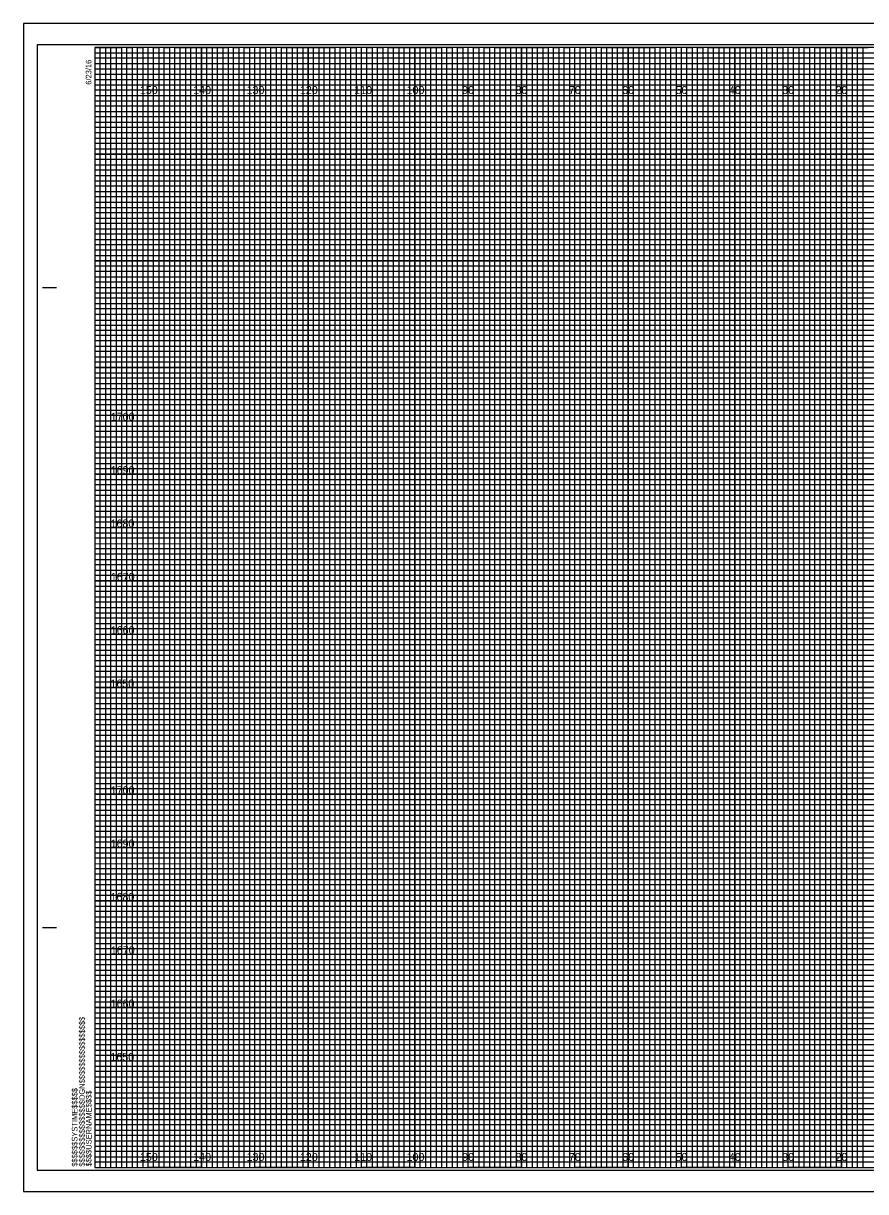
# Model space of a CAD drawing. Extents: x 656 to 993, y -2 to 2857.
# Drawn here: x 656.3 to 814.2, y 878.3 to 1097.3 of the extents above; entities that cross this region are included whole.
import ezdxf

# ---------------------------------------------------------------- set-up
doc = ezdxf.new("R2010")
doc.units = 0
for name, color, linetype in [('Prop RDY Alternate Text Blue', 7, 'Continuous'), ('Prop Retaining Wall', 7, 'Continuous'), ('Prop SS Cut Line', 7, 'Continuous'), ('Prop SS Fill Line', 7, 'Continuous'), ('Prop SS Transition Line', 7, 'Continuous'), ('Raster_Level_0', 7, 'Continuous'), ('Raster_Level_3', 7, 'Continuous'), ('Scratch_Level_3', 7, 'Continuous'), ('Scratch_Level_7', 7, 'Continuous'), ('Typical Guardrail CELL', 7, 'Continuous'), ('Typical Text Asphalt at Bridge Approach CELL', 7, 'Continuous')]:
    doc.layers.add(name, color=color, linetype=linetype)

msp = doc.modelspace()

# ---------------------------------------------------------------- linework, layer by layer
at = {"layer": 'Prop RDY Alternate Text Blue'}
for p, q in [((679.74, 882.8), (679.74, 1092.8)), ((689.74, 882.8), (689.74, 1092.8)), ((699.74, 882.8), (699.74, 1092.8)), ((709.74, 882.8), (709.74, 1092.8)), ((719.74, 882.8), (719.74, 1092.8)), ((729.74, 882.8), (729.74, 1092.8)), ((739.74, 882.8), (739.74, 1092.8)), ((749.74, 882.8), (749.74, 1092.8)), ((759.74, 882.8), (759.74, 1092.8)), ((769.74, 882.8), (769.74, 1092.8)), ((779.74, 882.8), (779.74, 1092.8)), ((789.74, 882.8), (789.74, 1092.8)), ((799.74, 882.8), (799.74, 1092.8)), ((809.74, 882.8), (809.74, 1092.8)), ((669.74, 1082.8), (989.74, 1082.8)), ((669.74, 1072.8), (989.74, 1072.8)), ((669.74, 1062.8), (989.74, 1062.8)), ((669.74, 1052.8), (989.74, 1052.8)), ((669.74, 1042.8), (989.74, 1042.8)), ((669.74, 1032.8), (989.74, 1032.8)), ((669.74, 1022.8), (989.74, 1022.8)), ((669.74, 1012.8), (989.74, 1012.8)), ((669.74, 1002.8), (989.74, 1002.8)), ((669.74, 992.8), (989.74, 992.8)), ((669.74, 982.8), (989.74, 982.8)), ((669.74, 972.8), (989.74, 972.8)), ((669.74, 962.8), (989.74, 962.8)), ((669.74, 952.8), (989.74, 952.8)), ((669.74, 942.8), (989.74, 942.8)), ((669.74, 932.8), (989.74, 932.8)), ((669.74, 922.8), (989.74, 922.8)), ((669.74, 912.8), (989.74, 912.8)), ((669.74, 902.8), (989.74, 902.8)), ((669.74, 892.8), (989.74, 892.8))]:
    msp.add_line(p, q, dxfattribs=at)
at = {"layer": 'Prop Retaining Wall'}
for p, q in [((659.94, 1047.8), (662.44, 1047.8)), ((660.04, 1047.8), (662.54, 1047.8)), ((659.94, 927.8), (662.44, 927.8)), ((660.04, 927.8), (662.54, 927.8)), ((669.74, 882.8), (669.74, 882.8)), ((669.74, 882.8), (669.74, 882.8)), ((669.74, 882.8), (669.74, 882.8)), ((669.74, 882.8), (669.74, 882.8)), ((669.74, 882.8), (669.74, 882.8)), ((669.74, 882.8), (669.74, 882.8)), ((669.74, 882.8), (669.74, 882.8))]:
    msp.add_line(p, q, dxfattribs=at)
msp.add_lwpolyline([(989.74, 1092.8), (669.74, 1092.8), (669.74, 882.8), (989.74, 882.8)], close=True, dxfattribs=at)
at = {"layer": 'Prop SS Cut Line'}
for points in [[(669.74, 1092.8), (674.74, 1092.8), (674.74, 882.8), (684.74, 882.8), (684.74, 1092.8), (694.74, 1092.8), (694.74, 882.8), (704.74, 882.8), (704.74, 1092.8), (714.74, 1092.8), (714.74, 882.8), (724.74, 882.8), (724.74, 1092.8), (734.74, 1092.8), (734.74, 882.8), (744.74, 882.8), (744.74, 1092.8), (754.74, 1092.8), (754.74, 882.8), (764.74, 882.8), (764.74, 1092.8), (774.74, 1092.8), (774.74, 882.8), (784.74, 882.8), (784.74, 1092.8), (794.74, 1092.8), (794.74, 882.8), (804.74, 882.8), (804.74, 1092.8), (814.74, 1092.8)], [(669.74, 1087.8), (944.74, 1087.8)], [(669.74, 1067.8), (989.74, 1067.8), (989.74, 1077.8), (669.74, 1077.8)], [(669.74, 1047.8), (989.74, 1047.8), (989.74, 1057.8), (669.74, 1057.8)], [(669.74, 1027.8), (989.74, 1027.8), (989.74, 1037.8), (669.74, 1037.8)], [(669.74, 1007.8), (989.74, 1007.8), (989.74, 1017.8), (669.74, 1017.8)], [(669.74, 987.8), (989.74, 987.8), (989.74, 997.8), (669.74, 997.8)], [(669.74, 967.8), (989.74, 967.8), (989.74, 977.8), (669.74, 977.8)], [(669.74, 947.8), (989.74, 947.8), (989.74, 957.8), (669.74, 957.8)], [(669.74, 927.8), (989.74, 927.8), (989.74, 937.8), (669.74, 937.8)], [(669.74, 907.8), (989.74, 907.8), (989.74, 917.8), (669.74, 917.8)], [(669.74, 887.8), (989.74, 887.8), (989.74, 897.8), (669.74, 897.8)]]:
    msp.add_lwpolyline(points, dxfattribs=at)
at = {"layer": 'Prop SS Fill Line'}
for p, q in [((679.74, 1092.8), (669.74, 1092.8)), ((679.74, 882.8), (679.74, 1092.8)), ((699.74, 1092.8), (689.74, 1092.8)), ((689.74, 1092.8), (689.74, 882.8)), ((699.74, 882.8), (699.74, 1092.8)), ((719.74, 1092.8), (709.74, 1092.8)), ((709.74, 1092.8), (709.74, 882.8)), ((719.74, 882.8), (719.74, 1092.8)), ((739.74, 1092.8), (729.74, 1092.8)), ((729.74, 1092.8), (729.74, 882.8)), ((739.74, 882.8), (739.74, 1092.8)), ((759.74, 1092.8), (749.74, 1092.8)), ((749.74, 1092.8), (749.74, 882.8)), ((759.74, 882.8), (759.74, 1092.8)), ((779.74, 1092.8), (769.74, 1092.8)), ((769.74, 1092.8), (769.74, 882.8)), ((779.74, 882.8), (779.74, 1092.8)), ((799.74, 1092.8), (789.74, 1092.8)), ((789.74, 1092.8), (789.74, 882.8)), ((799.74, 882.8), (799.74, 1092.8)), ((819.74, 1092.8), (809.74, 1092.8)), ((809.74, 1092.8), (809.74, 882.8)), ((689.74, 882.8), (679.74, 882.8)), ((709.74, 882.8), (699.74, 882.8)), ((729.74, 882.8), (719.74, 882.8)), ((749.74, 882.8), (739.74, 882.8)), ((769.74, 882.8), (759.74, 882.8)), ((789.74, 882.8), (779.74, 882.8)), ((809.74, 882.8), (799.74, 882.8))]:
    msp.add_line(p, q, dxfattribs=at)
for points in [[(669.74, 1082.8), (989.74, 1082.8), (989.74, 1072.8), (669.74, 1072.8)], [(669.74, 1062.8), (989.74, 1062.8), (989.74, 1052.8), (669.74, 1052.8)], [(669.74, 1042.8), (989.74, 1042.8), (989.74, 1032.8), (669.74, 1032.8)], [(669.74, 1022.8), (989.74, 1022.8), (989.74, 1012.8), (669.74, 1012.8)], [(669.74, 1002.8), (989.74, 1002.8), (989.74, 992.8), (669.74, 992.8)], [(669.74, 982.8), (989.74, 982.8), (989.74, 972.8), (669.74, 972.8)], [(669.74, 962.8), (989.74, 962.8), (989.74, 952.8), (669.74, 952.8)], [(669.74, 942.8), (989.74, 942.8), (989.74, 932.8), (669.74, 932.8)], [(669.74, 922.8), (989.74, 922.8), (989.74, 912.8), (669.74, 912.8)], [(669.74, 902.8), (989.74, 902.8), (989.74, 892.8), (669.74, 892.8)]]:
    msp.add_lwpolyline(points, dxfattribs=at)
at = {"layer": 'Prop SS Transition Line'}
for p, q in [((669.74, 1091.8), (929.74, 1091.8)), ((929.74, 1090.78), (669.74, 1090.78)), ((669.74, 1090.78), (669.74, 1089.8)), ((669.74, 1089.8), (929.74, 1089.8)), ((929.74, 1088.69), (669.74, 1088.69)), ((669.74, 1088.69), (669.74, 1086.8)), ((669.74, 1086.8), (989.74, 1086.8))]:
    msp.add_line(p, q, dxfattribs=at)
for points in [[(669.74, 1085.8), (939.74, 1085.8), (989.74, 1085.8), (989.74, 1084.8), (669.74, 1084.8)], [(669.74, 1083.8), (989.74, 1083.8), (989.74, 1081.8), (669.74, 1081.8)], [(669.74, 1080.8), (989.74, 1080.8), (989.74, 1079.8), (669.74, 1079.78)], [(669.74, 1078.8), (989.74, 1078.8), (989.74, 1076.8), (669.74, 1076.8)], [(669.74, 1075.8), (989.74, 1075.8), (989.74, 1074.8), (669.74, 1074.8)], [(669.74, 1073.8), (989.74, 1073.8), (989.74, 1071.8), (669.74, 1071.8)], [(669.74, 1070.8), (989.74, 1070.8), (989.74, 1069.8), (669.74, 1069.8)], [(669.74, 1068.8), (989.74, 1068.8), (989.74, 1066.8), (669.74, 1066.8)], [(669.74, 1065.8), (989.74, 1065.8), (989.74, 1064.8), (669.74, 1064.8)], [(669.74, 1063.8), (989.74, 1063.8), (989.74, 1061.8), (669.74, 1061.8)], [(669.74, 1060.8), (989.74, 1060.8), (989.74, 1059.8), (669.74, 1059.8)], [(669.74, 1058.8), (989.74, 1058.8), (989.74, 1056.75), (989.74, 1055.8), (989.74, 1054.8), (669.74, 1054.8)], [(669.74, 1056.8), (989.74, 1056.8), (989.74, 1055.8), (669.74, 1055.8)], [(669.74, 1053.8), (989.74, 1053.8), (989.74, 1051.8), (669.74, 1051.83)], [(669.74, 1051.83), (989.74, 1051.8), (989.74, 1050.8), (669.74, 1050.8)], [(669.74, 1049.8), (989.74, 1049.8), (989.74, 1048.8), (669.74, 1048.8)], [(669.74, 1046.8), (989.74, 1046.8), (989.74, 1045.8), (669.74, 1045.8)], [(669.74, 1044.8), (989.74, 1044.8), (989.74, 1043.8), (669.74, 1043.8)], [(669.67, 1041.69), (989.74, 1041.69), (989.74, 1040.68), (669.67, 1040.68)], [(669.74, 1039.8), (989.74, 1039.8), (989.74, 1038.8), (669.74, 1038.8)], [(669.74, 1036.8), (989.74, 1036.8), (989.74, 1035.8), (669.74, 1035.8)], [(669.74, 1034.8), (989.74, 1034.8), (989.74, 1033.8), (669.74, 1033.8)], [(669.74, 1031.8), (989.74, 1031.8), (989.74, 1030.8), (669.74, 1030.8)], [(669.74, 1029.8), (989.74, 1029.8), (989.74, 1028.8), (669.74, 1028.8)], [(669.74, 1026.8), (989.74, 1026.8), (989.74, 1025.8), (669.74, 1025.8)], [(669.74, 1024.8), (989.74, 1024.8), (989.74, 1023.8), (669.74, 1023.8)], [(669.74, 1021.8), (989.74, 1021.8), (989.73, 1020.78), (669.74, 1020.8)], [(669.74, 1019.8), (989.74, 1019.8), (989.74, 1018.8), (669.74, 1018.8)], [(669.74, 1016.8), (989.74, 1016.8), (989.74, 1015.8), (669.74, 1015.8)], [(669.74, 1014.8), (989.74, 1014.8), (989.74, 1013.8), (669.74, 1013.8)], [(669.74, 1011.8), (989.74, 1011.8), (989.74, 1010.8), (669.74, 1010.8)], [(669.74, 1009.8), (989.74, 1009.8), (989.74, 1008.8), (669.74, 1008.8)], [(669.74, 1006.8), (989.74, 1006.8), (989.74, 1005.8), (669.74, 1005.8)], [(669.74, 1004.8), (989.74, 1004.8), (989.74, 1003.8), (669.74, 1003.8)], [(669.74, 1001.8), (989.74, 1001.8), (989.74, 1000.8), (669.74, 1000.8)], [(669.74, 999.79), (989.81, 999.71), (989.74, 998.8), (669.74, 998.8)], [(669.74, 996.8), (989.74, 996.8), (989.74, 995.8), (669.74, 995.8)], [(669.74, 994.8), (989.74, 994.8), (989.74, 993.8), (669.74, 993.8)], [(669.74, 991.8), (989.74, 991.8), (989.74, 990.8), (669.74, 990.8)], [(669.74, 989.8), (989.74, 989.8), (989.74, 988.8), (669.74, 988.8)], [(669.74, 986.8), (989.74, 986.8), (989.74, 985.8), (669.74, 985.8)], [(669.74, 984.8), (989.74, 984.8), (989.74, 983.8), (669.74, 983.8)], [(669.74, 981.8), (989.74, 981.8), (989.74, 980.8), (669.74, 980.8)], [(669.74, 979.8), (989.74, 979.8), (989.74, 978.8), (669.74, 978.8)], [(669.74, 976.8), (989.74, 976.8), (989.74, 975.8), (669.74, 975.8)], [(669.74, 974.8), (989.74, 974.8), (989.74, 973.8), (669.74, 973.8)], [(669.74, 971.8), (989.74, 971.8), (989.74, 970.8), (669.74, 970.8)], [(669.74, 969.8), (989.74, 969.8), (989.74, 968.8), (669.74, 968.8)], [(669.74, 966.8), (989.74, 966.8), (989.74, 965.8), (669.74, 965.8)], [(669.74, 964.8), (989.74, 964.8), (989.74, 963.8), (669.74, 963.8)], [(669.74, 961.8), (989.74, 961.8), (989.73, 960.78), (669.74, 960.8)], [(669.74, 959.8), (989.74, 959.8), (989.74, 958.8), (669.74, 958.8)], [(669.74, 956.8), (989.74, 956.8), (989.74, 955.8), (669.74, 955.8)], [(669.74, 954.8), (989.74, 954.8), (989.74, 953.8), (669.74, 953.8)], [(669.74, 951.8), (989.74, 951.8), (989.74, 950.8), (669.74, 950.8)], [(669.74, 949.8), (989.74, 949.8), (989.74, 948.8), (669.74, 948.8)], [(669.74, 946.8), (989.74, 946.8), (989.74, 945.8), (669.74, 945.8)], [(669.74, 944.8), (989.74, 944.8), (989.74, 943.8), (669.74, 943.8)], [(669.74, 941.8), (989.74, 941.8), (989.74, 940.8), (669.74, 940.8)], [(669.74, 939.79), (989.81, 939.71), (989.74, 938.8), (669.74, 938.8)], [(669.74, 936.8), (989.74, 936.8), (989.74, 935.8), (669.74, 935.8)], [(669.74, 934.8), (989.74, 934.8), (989.74, 933.8), (669.74, 933.8)], [(669.74, 931.8), (989.74, 931.8), (989.74, 930.8), (669.74, 930.8)], [(669.74, 929.8), (989.74, 929.8), (989.74, 928.8), (669.74, 928.8)], [(669.74, 926.8), (989.74, 926.8), (989.74, 925.8), (669.74, 925.8)], [(669.74, 924.8), (989.74, 924.8), (989.74, 923.8), (669.74, 923.8)], [(669.74, 921.8), (989.74, 921.8), (989.74, 920.8), (669.74, 920.8)], [(669.74, 919.8), (989.74, 919.8), (989.74, 918.8), (669.74, 918.8)], [(669.74, 916.8), (989.74, 916.8), (989.74, 915.8), (669.74, 915.8)], [(669.74, 914.8), (989.74, 914.8), (989.74, 913.8), (669.74, 913.8)], [(669.74, 911.8), (989.74, 911.8), (989.74, 910.8), (669.74, 910.8)], [(669.74, 909.8), (989.74, 909.8), (989.74, 908.8), (669.74, 908.8)], [(669.74, 906.8), (989.74, 906.8), (989.74, 905.8), (669.74, 905.8)], [(669.74, 904.8), (989.74, 904.8), (989.74, 903.8), (669.74, 903.8)], [(669.74, 901.8), (989.74, 901.8), (989.74, 900.8), (669.74, 900.8)], [(669.74, 899.8), (989.74, 899.8), (989.74, 898.8), (669.74, 898.8)], [(669.74, 896.8), (989.74, 896.8), (989.74, 895.8), (669.74, 895.8)], [(669.74, 894.8), (989.74, 894.8), (989.74, 893.8), (669.74, 893.8)], [(669.74, 891.8), (989.74, 891.8), (989.74, 890.8), (669.74, 890.8)], [(669.74, 889.8), (989.74, 889.8), (989.74, 888.8), (669.74, 888.8)], [(669.74, 886.8), (989.74, 886.8), (989.74, 885.8), (669.74, 885.8)], [(669.74, 884.8), (989.74, 884.8), (989.74, 883.8), (669.74, 883.8)]]:
    msp.add_lwpolyline(points, dxfattribs=at)
at = {"layer": 'Raster_Level_3'}
for points in [[(669.74, 882.8), (670.74, 882.8), (670.74, 1092.8), (671.74, 1092.8), (671.74, 882.8)], [(671.74, 882.8), (672.74, 882.8), (672.74, 1092.8), (673.74, 1092.8), (673.74, 882.8)], [(674.74, 882.8), (675.74, 882.8), (675.74, 1092.8), (676.74, 1092.8), (676.74, 882.8)], [(676.74, 882.8), (677.74, 882.8), (677.74, 1092.8), (678.74, 1092.8), (678.74, 882.8)], [(679.74, 882.8), (680.74, 882.8), (680.74, 1092.8), (681.74, 1092.8), (681.74, 882.8)], [(681.74, 882.8), (682.74, 882.8), (682.74, 1092.8), (683.74, 1092.8), (683.74, 882.8)], [(684.74, 882.8), (685.74, 882.8), (685.74, 1092.8), (686.74, 1092.8), (686.74, 882.8)], [(686.74, 882.8), (687.74, 882.8), (687.74, 1092.8), (688.74, 1092.8), (688.74, 882.8)], [(689.74, 882.8), (690.74, 882.8), (690.74, 1092.8), (691.74, 1092.8), (691.74, 882.8)], [(691.74, 882.8), (692.74, 882.8), (692.74, 1092.8), (693.74, 1092.8), (693.74, 882.8)], [(694.74, 882.8), (695.74, 882.8), (695.74, 1092.8), (696.74, 1092.8), (696.74, 882.8)], [(696.74, 882.8), (697.74, 882.8), (697.74, 1092.8), (698.74, 1092.8), (698.74, 882.8)], [(699.74, 882.8), (700.74, 882.8), (700.74, 1092.8), (701.74, 1092.8), (701.74, 882.8)], [(701.74, 882.8), (702.74, 882.8), (702.74, 1092.8), (703.74, 1092.8), (703.74, 882.8)], [(704.74, 882.8), (705.74, 882.8), (705.74, 1092.8), (706.74, 1092.8), (706.74, 882.8)], [(706.74, 882.8), (707.74, 882.8), (707.74, 1092.8), (708.74, 1092.8), (708.74, 882.8)], [(709.74, 882.8), (710.74, 882.8), (710.74, 1092.8), (711.74, 1092.8), (711.74, 882.8)], [(711.74, 882.8), (712.74, 882.8), (712.74, 1092.8), (713.74, 1092.8), (713.74, 882.8)], [(714.74, 882.8), (715.74, 882.8), (715.74, 1092.8), (716.74, 1092.8), (716.74, 882.8)], [(716.74, 882.8), (717.74, 882.8), (717.74, 1092.8), (718.74, 1092.8), (718.74, 882.8)], [(719.74, 882.8), (720.74, 882.8), (720.74, 1092.8), (721.74, 1092.8), (721.74, 882.8)], [(721.74, 882.8), (722.74, 882.8), (722.74, 1092.8), (723.74, 1092.8), (723.74, 882.8)], [(724.74, 882.8), (725.74, 882.8), (725.74, 1092.8), (726.74, 1092.8), (726.74, 882.8)], [(726.74, 882.8), (727.74, 882.8), (727.74, 1092.8), (728.74, 1092.8), (728.74, 882.8)], [(729.74, 882.8), (730.74, 882.8), (730.74, 1092.8), (731.74, 1092.8), (731.74, 882.8)], [(731.74, 882.8), (732.74, 882.8), (732.74, 1092.8), (733.74, 1092.8), (733.74, 882.8)], [(734.74, 882.8), (735.74, 882.8), (735.74, 1092.8), (736.74, 1092.8), (736.74, 882.8)], [(736.74, 882.8), (737.74, 882.8), (737.74, 1092.8), (738.74, 1092.8), (738.74, 882.8)], [(739.74, 882.8), (740.74, 882.8), (740.74, 1092.8), (741.74, 1092.8), (741.74, 882.8)], [(741.74, 882.8), (742.74, 882.8), (742.74, 1092.8), (743.74, 1092.8), (743.74, 882.8)], [(744.74, 882.8), (745.74, 882.8), (745.74, 1092.8), (746.74, 1092.8), (746.74, 882.8)], [(746.74, 882.8), (747.74, 882.8), (747.74, 1092.8), (748.74, 1092.8), (748.74, 882.8)], [(749.74, 882.8), (750.74, 882.8), (750.74, 1092.8), (751.74, 1092.8), (751.74, 882.8)], [(751.74, 882.8), (752.74, 882.8), (752.74, 1092.8), (753.74, 1092.8), (753.74, 882.8)], [(754.74, 882.8), (755.74, 882.8), (755.74, 1092.8), (756.74, 1092.8), (756.74, 882.8)], [(756.74, 882.8), (757.74, 882.8), (757.74, 1092.8), (758.74, 1092.8), (758.74, 882.8)], [(759.74, 882.8), (760.74, 882.8), (760.74, 1092.8), (761.74, 1092.8), (761.74, 882.8)], [(761.74, 882.8), (762.74, 882.8), (762.74, 1092.8), (763.74, 1092.8), (763.74, 882.8)], [(764.74, 882.8), (765.74, 882.8), (765.74, 1092.8), (766.74, 1092.8), (766.74, 882.8)], [(766.74, 882.8), (767.74, 882.8), (767.74, 1092.8), (768.74, 1092.8), (768.74, 882.8)], [(769.74, 882.8), (770.74, 882.8), (770.74, 1092.8), (771.74, 1092.8), (771.74, 882.8)], [(771.74, 882.8), (772.74, 882.8), (772.74, 1092.8), (773.74, 1092.8), (773.74, 882.8)], [(774.74, 882.8), (775.74, 882.8), (775.74, 1092.8), (776.74, 1092.8), (776.74, 882.8)], [(776.74, 882.8), (777.74, 882.8), (777.74, 1092.8), (778.74, 1092.8), (778.74, 882.8)], [(779.74, 882.8), (780.74, 882.8), (780.74, 1092.8), (781.74, 1092.8), (781.74, 882.8)], [(781.74, 882.8), (782.74, 882.8), (782.74, 1092.8), (783.74, 1092.8), (783.74, 882.8)], [(784.74, 882.8), (785.74, 882.8), (785.74, 1092.8), (786.74, 1092.8), (786.74, 882.8)], [(786.74, 882.8), (787.74, 882.8), (787.74, 1092.8), (788.74, 1092.8), (788.74, 882.8)], [(789.74, 882.8), (790.74, 882.8), (790.74, 1092.8), (791.74, 1092.8), (791.74, 882.8)], [(791.74, 882.8), (792.74, 882.8), (792.74, 1092.8), (793.74, 1092.8), (793.74, 882.8)], [(794.74, 882.8), (795.74, 882.8), (795.74, 1092.8), (796.74, 1092.8), (796.74, 882.8)], [(796.74, 882.8), (797.74, 882.8), (797.74, 1092.8), (798.74, 1092.8), (798.74, 882.8)], [(799.74, 882.8), (800.74, 882.8), (800.74, 1092.8), (801.74, 1092.8), (801.74, 882.8)], [(801.74, 882.8), (802.74, 882.8), (802.74, 1092.8), (803.74, 1092.8), (803.74, 882.8)], [(804.74, 882.8), (805.74, 882.8), (805.74, 1092.8), (806.74, 1092.8), (806.74, 882.8)], [(806.74, 882.8), (807.74, 882.8), (807.74, 1092.8), (808.74, 1092.8), (808.74, 882.8)], [(809.74, 882.8), (810.74, 882.8), (810.74, 1092.8), (811.74, 1092.8), (811.74, 882.8)], [(811.74, 882.8), (812.74, 882.8), (812.74, 1092.8), (813.74, 1092.8), (813.74, 882.8)]]:
    msp.add_lwpolyline(points, dxfattribs=at)
at = {"layer": 'Scratch_Level_7'}
msp.add_lwpolyline([(656.34, 878.3), (993.04, 878.3), (993.04, 1097.3), (656.34, 1097.3)], close=True, dxfattribs=at)
at = {"layer": 'Typical Guardrail CELL'}
msp.add_lwpolyline([(658.94, 882.3), (992.14, 882.3), (992.14, 1093.3), (658.94, 1093.3)], close=True, dxfattribs=at)
at = {"layer": 'Typical Text Asphalt at Bridge Approach CELL'}
for p, q in [((993.04, 1097.3), (656.34, 1097.3)), ((656.34, 1097.3), (656.34, 878.3)), ((656.34, 878.3), (993.04, 878.3))]:
    msp.add_line(p, q, dxfattribs=at)

# ---------------------------------------------------------------- texts
at = {"layer": 'Prop Retaining Wall'}
for s, p in [('6/23/16', (669.09, 1085.8)), ('$$$$$$$$$$$$$$$$DGN$$$$$$$$$$$$$$$$', (667.86, 882.98)), ('$$$$$$SYSTIME$$$$$', (666.48, 882.98)), ('$$$$USERNAME$$$$', (669.12, 883.03))]:
    msp.add_text(s, height=1.05, rotation=90, dxfattribs=at).set_placement(p)
at = {"layer": 'Raster_Level_0'}
for s, p in [('150', (678.18, 1084.05)), ('140', (688.18, 1084.05)), ('130', (698.18, 1084.05)), ('120', (708.18, 1084.05)), ('110', (718.36, 1084.05)), ('100', (728.18, 1084.05)), ('90', (738.6, 1084.05)), ('80', (748.6, 1084.05)), ('70', (758.6, 1084.05)), ('60', (768.6, 1084.05)), ('50', (778.6, 1084.05)), ('40', (788.6, 1084.05)), ('30', (798.6, 1084.05)), ('20', (808.6, 1084.05)), ('150', (678.18, 884.05)), ('140', (688.18, 884.05)), ('130', (698.18, 884.05)), ('120', (708.18, 884.05)), ('110', (718.36, 884.05)), ('100', (728.18, 884.05)), ('90', (738.6, 884.05)), ('80', (748.6, 884.05)), ('70', (758.6, 884.05)), ('60', (768.6, 884.05)), ('50', (778.6, 884.05)), ('40', (788.6, 884.05)), ('30', (798.6, 884.05)), ('20', (808.6, 884.05))]:
    msp.add_text(s, height=1.5, dxfattribs=at).set_placement(p)
at = {"layer": 'Scratch_Level_3'}
for s, p in [('1700', (672.72, 1022.8)), ('1690', (672.71, 1012.8)), ('1680', (672.68, 1002.8)), ('1670', (672.74, 992.8)), ('1660', (672.71, 982.8)), ('1650', (672.66, 972.8)), ('1700', (672.72, 952.8)), ('1690', (672.71, 942.8)), ('1680', (672.68, 932.8)), ('1670', (672.74, 922.8)), ('1660', (672.71, 912.8)), ('1650', (672.66, 902.8))]:
    msp.add_text(s, height=1.5, dxfattribs=at).set_placement(p)

doc.saveas('drawing.dxf')
